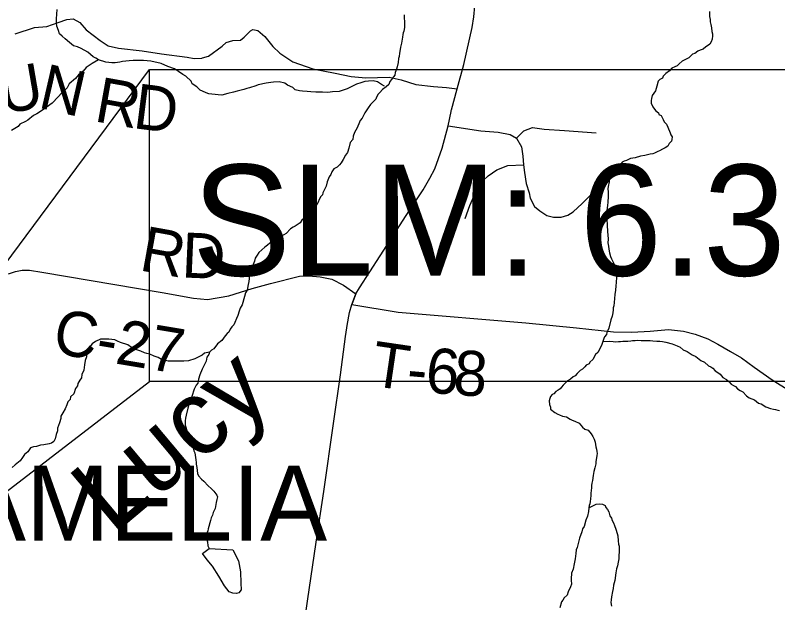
# Model space of a CAD drawing. Extents: x 0 to 39.3, y -3.9 to 22.
# Drawn here: x 5.137 to 6.099, y 18.467 to 19.208 of the extents above; entities that cross this region are included whole.
import ezdxf

# ---------------------------------------------------------------- set-up
doc = ezdxf.new("R2010")
doc.units = 0
for name, color, linetype in [('GM_X_Corporation_Text', 7, 'Continuous'), ('GM_X_County_Road', 7, 'Continuous'), ('GM_X_County_Road_Text', 7, 'Continuous'), ('GM_X_Minor_Lake', 7, 'Continuous'), ('GM_X_Minor_River', 7, 'Continuous'), ('GM_X_Minor_River_Text', 7, 'Continuous'), ('GM_X_State_Route', 7, 'Continuous'), ('GM_X_Township_Road', 7, 'Continuous'), ('GM_X_Township_Road_Text', 7, 'Continuous'), ('SH_Text', 7, 'Continuous')]:
    doc.layers.add(name, color=color, linetype=linetype)

msp = doc.modelspace()

# ---------------------------------------------------------------- linework, layer by layer
at = {"layer": 'GM_X_County_Road'}
msp.add_line((5.56691, 18.85683), (5.56159, 18.84354), dxfattribs=at)
for points in [[(5.12824, 18.88192), (5.13704, 18.8851), (5.1458, 18.88677), (5.15489, 18.88653), (5.17036, 18.88423), (5.32226, 18.85848), (5.36186, 18.85135), (5.3797, 18.84956), (5.4064, 18.85412), (5.43606, 18.86347), (5.45889, 18.86989), (5.49574, 18.87911), (5.50749, 18.87956), (5.52185, 18.87805), (5.5363, 18.87524), (5.55128, 18.86775), (5.56691, 18.85683)], [(5.56159, 18.84354), (5.62006, 18.83388), (5.78139, 18.82038), (5.84509, 18.81404), (5.8917, 18.80892), (5.91489, 18.80843), (5.93834, 18.80985), (5.96146, 18.81204), (5.9802, 18.80954), (5.99488, 18.8061), (6.01112, 18.79985), (6.02361, 18.7933), (6.03954, 18.78393), (6.0536, 18.77612), (6.06953, 18.76425), (6.09202, 18.74832), (6.11453, 18.73458)]]:
    msp.add_lwpolyline(points, dxfattribs=at)
at = {"layer": 'GM_X_Minor_Lake'}
msp.add_line((5.37322, 18.52915), (5.38151, 18.53579), dxfattribs=at)
msp.add_lwpolyline([(5.38151, 18.53579), (5.4117, 18.5338), (5.41869, 18.52), (5.42112, 18.50627), (5.42163, 18.49182), (5.42187, 18.48345), (5.41915, 18.47969), (5.41609, 18.47899), (5.41153, 18.47907), (5.407, 18.48105), (5.40104, 18.48837), (5.39365, 18.50066), (5.38588, 18.51334), (5.37918, 18.52144), (5.37322, 18.52915)], dxfattribs=at)
at = {"layer": 'GM_X_Minor_River'}
for points in [[(5.60269, 19.11877), (5.5993, 19.12073), (5.59404, 19.12425), (5.58874, 19.12548), (5.58265, 19.12521), (5.57808, 19.12453), (5.57311, 19.1231), (5.56776, 19.12129), (5.56086, 19.11799), (5.55587, 19.11541), (5.54556, 19.11217), (5.53718, 19.11156), (5.53147, 19.1109), (5.52463, 19.11102), (5.51627, 19.11116), (5.50981, 19.11166), (5.50526, 19.11212), (5.49956, 19.1126), (5.49577, 19.11305), (5.49009, 19.11429), (5.48709, 19.117), (5.48068, 19.12016), (5.4773, 19.1225), (5.4701, 19.12415), (5.46288, 19.12389), (5.45945, 19.12357), (5.45335, 19.12254), (5.44343, 19.12043), (5.44037, 19.11935), (5.43234, 19.11683), (5.42928, 19.11574), (5.42546, 19.11467), (5.41706, 19.11253), (5.41248, 19.11109), (5.40523, 19.10932), (5.39759, 19.10755), (5.39303, 19.10763), (5.38127, 19.10898), (5.37787, 19.11018), (5.37334, 19.11254), (5.37032, 19.11373), (5.36621, 19.11799), (5.36019, 19.12152), (5.35873, 19.12497), (5.35199, 19.13117), (5.34823, 19.13352), (5.34297, 19.13742), (5.33808, 19.14054), (5.32939, 19.14374), (5.32108, 19.14731), (5.30783, 19.1502), (5.29872, 19.15112), (5.2915, 19.15125), (5.28579, 19.15097), (5.28046, 19.15068), (5.27246, 19.14968), (5.26903, 19.14898), (5.26294, 19.14833), (5.25875, 19.14803), (5.25116, 19.14892), (5.24209, 19.15212), (5.2387, 19.15408), (5.23531, 19.15566), (5.22856, 19.16149), (5.22028, 19.1662), (5.21537, 19.16857), (5.21045, 19.16979), (5.2052, 19.17369), (5.19995, 19.17834), (5.19621, 19.18183), (5.19283, 19.18456), (5.19139, 19.18915), (5.1892, 19.19451), (5.18889, 19.1987), (5.18897, 19.20364), (5.18993, 19.21541)], [(5.62778, 19.20884), (5.62772, 19.20542), (5.628, 19.19933), (5.62831, 19.19514), (5.62827, 19.19286), (5.62743, 19.18831), (5.62663, 19.18604)], [(6.01296, 19.2131), (6.01323, 19.20663), (6.01393, 19.20281), (6.01388, 19.19977), (6.01458, 19.19633), (6.01565, 19.19213), (6.01595, 19.18756), (6.01667, 19.18489), (6.01701, 19.18222), (6.01655, 19.17804)], [(5.62663, 19.18604), (5.62622, 19.18377), (5.6254, 19.18036), (5.62452, 19.17315), (5.62329, 19.16785), (5.62286, 19.16482), (5.62202, 19.16026), (5.62157, 19.15609), (5.62076, 19.15344), (5.6203, 19.1485), (5.61907, 19.1432), (5.61788, 19.14018), (5.61629, 19.13603), (5.61585, 19.13261), (5.61429, 19.13036), (5.61158, 19.12736), (5.60963, 19.12473), (5.60843, 19.12095), (5.60496, 19.11797), (5.60034, 19.11463), (5.59686, 19.11089), (5.59492, 19.10864), (5.59295, 19.10487), (5.59177, 19.10223), (5.58829, 19.09849), (5.58519, 19.0955), (5.58208, 19.09137), (5.57817, 19.08497), (5.57464, 19.07819), (5.57231, 19.07557), (5.57151, 19.0733), (5.56835, 19.06613), (5.56522, 19.06048), (5.56323, 19.05557), (5.56278, 19.0514), (5.55968, 19.04765), (5.55804, 19.04045), (5.55605, 19.03516), (5.55371, 19.03178), (5.55057, 19.02613), (5.54822, 19.02199), (5.5459, 19.01936), (5.54319, 19.01675), (5.53897, 19.01454), (5.53663, 19.01078), (5.53505, 19.00739), (5.5331, 19.00438), (5.53071, 18.99795), (5.5291, 18.99266), (5.52673, 18.98775), (5.52516, 18.98436), (5.52473, 18.9817), (5.52241, 18.97946), (5.52084, 18.97645), (5.51886, 18.97154), (5.5173, 18.96928), (5.51422, 18.96706), (5.51228, 18.96443), (5.50992, 18.95991), (5.50797, 18.95728), (5.5045, 18.9543), (5.50142, 18.95207), (5.49872, 18.94983), (5.49639, 18.94645), (5.49408, 18.94459), (5.49024, 18.94237), (5.48755, 18.9409), (5.48447, 18.93867), (5.47867, 18.93307), (5.47598, 18.93122), (5.47254, 18.92975), (5.47023, 18.92827), (5.46676, 18.92529), (5.46214, 18.92195), (5.45832, 18.92088), (5.45523, 18.91827), (5.45177, 18.91567), (5.44791, 18.91231), (5.44443, 18.90895), (5.44209, 18.90557), (5.43975, 18.90181), (5.43893, 18.89802), (5.43616, 18.8916), (5.43417, 18.88631), (5.43254, 18.88025), (5.43165, 18.87228), (5.43083, 18.8685), (5.42956, 18.86129), (5.42761, 18.8579), (5.42601, 18.85337), (5.42317, 18.84276), (5.42082, 18.83862), (5.41961, 18.83484), (5.418, 18.82954), (5.41604, 18.82578), (5.41406, 18.82086), (5.41287, 18.81784), (5.41016, 18.81523), (5.40821, 18.81222), (5.40662, 18.80844), (5.40432, 18.80696)], [(6.01655, 19.17804), (6.01498, 19.17465), (6.01341, 19.17164), (6.01071, 19.16978), (6.00841, 19.1683), (6.00494, 19.16532), (6.00112, 19.16425), (5.99843, 19.16277), (5.99458, 19.1598), (5.99152, 19.15909), (5.98689, 19.15461), (5.97845, 19.15019), (5.97459, 19.14684), (5.97227, 19.14422), (5.96921, 19.14313), (5.96537, 19.14129), (5.96266, 19.13792), (5.95804, 19.13458), (5.95456, 19.13122), (5.95376, 19.12895), (5.95031, 19.12711), (5.94837, 19.12486), (5.94637, 19.11881), (5.94474, 19.11275), (5.94085, 19.10711), (5.93964, 19.10333), (5.93922, 19.10068), (5.93954, 19.09725), (5.94136, 19.09265), (5.94509, 19.08803), (5.94846, 19.0853), (5.94919, 19.08301), (5.95183, 19.08182), (5.95441, 19.07683), (5.95587, 19.07376), (5.95886, 19.07067), (5.96033, 19.06722), (5.96324, 19.05994), (5.96434, 19.05726), (5.96582, 19.05495), (5.96538, 19.05154), (5.96497, 19.04926), (5.96225, 19.04627), (5.9603, 19.04326), (5.95722, 19.04103), (5.95377, 19.03919), (5.94993, 19.03698), (5.94764, 19.03626), (5.9438, 19.03404), (5.94151, 19.03332), (5.93808, 19.033), (5.93159, 19.03121), (5.92587, 19.03055), (5.91937, 19.02839), (5.91327, 19.02735), (5.90829, 19.02516), (5.90523, 19.02407), (5.90294, 19.02297), (5.9006, 19.01959), (5.89789, 19.01697), (5.89633, 19.01472), (5.89477, 19.01208), (5.89246, 19.01022), (5.88976, 19.00799), (5.88857, 19.00497), (5.88662, 19.00196), (5.88655, 18.99816), (5.88531, 18.99209), (5.88488, 18.98906), (5.8852, 18.98563), (5.8851, 18.97993), (5.88459, 18.97195), (5.88415, 18.96853), (5.88366, 18.96169), (5.88321, 18.95752), (5.88316, 18.95486), (5.88346, 18.95029), (5.88374, 18.9442), (5.88407, 18.94115), (5.88439, 18.93734), (5.88435, 18.93506), (5.88466, 18.93125), (5.88495, 18.92592), (5.88487, 18.92098), (5.88556, 18.91678), (5.88588, 18.91335), (5.88694, 18.90839), (5.88801, 18.90381), (5.88948, 18.90112), (5.89205, 18.89575), (5.89387, 18.89115), (5.89496, 18.88809), (5.89492, 18.88543), (5.89524, 18.882), (5.89555, 18.87781), (5.89544, 18.87097), (5.89498, 18.86679), (5.89451, 18.86148), (5.89366, 18.85579), (5.89273, 18.84591), (5.89228, 18.84174)], [(5.24209, 19.15212), (5.23403, 19.14732), (5.22633, 19.14213), (5.22246, 19.13764), (5.21668, 19.13317), (5.2128, 19.1283), (5.20508, 19.12159), (5.20234, 19.11669), (5.19538, 19.10997), (5.19112, 19.1051), (5.18338, 19.09725), (5.17145, 19.08833), (5.16415, 19.08389), (5.15993, 19.08168), (5.15299, 19.07572), (5.14992, 19.07426), (5.14264, 19.07096), (5.14069, 19.06795), (5.13224, 19.06278)], [(5.89228, 18.84174), (5.89148, 18.83909), (5.89144, 18.83681), (5.891, 18.83301), (5.89016, 18.82846), (5.88856, 18.82393), (5.8861, 18.81332), (5.88454, 18.81068), (5.88335, 18.80804), (5.88293, 18.80539), (5.8806, 18.80277), (5.8798, 18.8005), (5.87701, 18.79294), (5.87582, 18.78992), (5.8719, 18.78276), (5.86919, 18.78015), (5.86567, 18.77412), (5.86181, 18.77077), (5.86101, 18.7685), (5.85757, 18.76704), (5.85563, 18.76479), (5.85292, 18.7618), (5.84985, 18.75995), (5.84598, 18.75622), (5.84366, 18.75359), (5.84097, 18.75212), (5.8375, 18.74914), (5.83404, 18.74691), (5.83056, 18.74355), (5.82825, 18.74169), (5.8263, 18.73906), (5.82437, 18.73682), (5.82206, 18.73533), (5.81899, 18.73349), (5.81666, 18.73087), (5.81436, 18.72976), (5.81243, 18.72752), (5.81162, 18.72487), (5.81081, 18.72184), (5.81111, 18.71727), (5.81219, 18.71383), (5.81253, 18.71116), (5.81779, 18.70726), (5.82155, 18.70492), (5.82382, 18.70412), (5.82759, 18.70253), (5.83252, 18.70168), (5.83704, 18.69894), (5.83967, 18.69737), (5.84307, 18.69617), (5.84835, 18.69379), (5.85283, 18.68877), (5.85583, 18.68606), (5.85999, 18.68484), (5.86371, 18.68021), (5.86593, 18.67675), (5.8674, 18.67368), (5.86886, 18.66985), (5.86952, 18.66375), (5.87023, 18.6607), (5.87094, 18.65802), (5.87128, 18.65536), (5.87085, 18.6527), (5.87043, 18.65005), (5.86959, 18.6455), (5.86954, 18.64245), (5.86831, 18.63715), (5.86709, 18.63261), (5.86625, 18.62768), (5.86538, 18.62123), (5.86457, 18.6182), (5.86414, 18.61516), (5.86409, 18.6125), (5.86364, 18.60833), (5.86322, 18.60567), (5.86316, 18.60225), (5.86272, 18.59845), (5.86228, 18.59504), (5.86185, 18.592), (5.86105, 18.58973), (5.86062, 18.5867), (5.86016, 18.58214), (5.85892, 18.57646), (5.85694, 18.57155), (5.8549, 18.56322), (5.85295, 18.56021), (5.85174, 18.55643), (5.84895, 18.54849), (5.84609, 18.53675), (5.8449, 18.53372), (5.84444, 18.52917), (5.84357, 18.52272), (5.84232, 18.51627), (5.84107, 18.50945), (5.83908, 18.50454), (5.83905, 18.50226), (5.83862, 18.4996), (5.83856, 18.4958), (5.83885, 18.49047), (5.83765, 18.48707), (5.83451, 18.48104)], [(5.40432, 18.80696), (5.40199, 18.80396), (5.3977, 18.79795), (5.39231, 18.79386), (5.38764, 18.78748), (5.38457, 18.78563), (5.38187, 18.7834), (5.38106, 18.78037), (5.37872, 18.77699), (5.37787, 18.77168), (5.37276, 18.76188), (5.36998, 18.7547), (5.36799, 18.74903), (5.36715, 18.7441), (5.3652, 18.74147), (5.36284, 18.73657), (5.35964, 18.7275), (5.35883, 18.72447), (5.35762, 18.72031), (5.35605, 18.71729), (5.35483, 18.71275), (5.35278, 18.70365), (5.35157, 18.69987), (5.35114, 18.69684), (5.35143, 18.69113), (5.3525, 18.6873), (5.35393, 18.68195), (5.35571, 18.67432), (5.35756, 18.67162), (5.35866, 18.66932), (5.35937, 18.66626), (5.36159, 18.66242), (5.36228, 18.6586), (5.36338, 18.6563), (5.36409, 18.65325), (5.36442, 18.6502), (5.36476, 18.64753), (5.36508, 18.6441), (5.36542, 18.64181), (5.36611, 18.63762), (5.36674, 18.63), (5.36822, 18.62731), (5.37195, 18.62306), (5.37494, 18.62035), (5.38017, 18.61455), (5.3843, 18.61143), (5.38766, 18.60795), (5.39138, 18.60294), (5.3921, 18.60065), (5.39128, 18.59724), (5.39046, 18.59345), (5.3892, 18.58624), (5.38683, 18.58096), (5.38601, 18.57755), (5.38405, 18.57416), (5.38323, 18.57075), (5.3804, 18.56053), (5.37998, 18.55788), (5.37918, 18.55561), (5.37912, 18.55219), (5.37832, 18.54954), (5.37865, 18.54687), (5.37937, 18.5442), (5.38004, 18.53886), (5.38151, 18.53579)], [(5.38184, 18.78327), (5.37576, 18.78198), (5.37268, 18.77938), (5.36348, 18.77497), (5.35546, 18.77245), (5.34974, 18.77179), (5.34328, 18.7719), (5.33377, 18.77169), (5.32997, 18.77176), (5.32467, 18.77299), (5.32127, 18.77419), (5.31713, 18.77655), (5.31221, 18.77816), (5.30693, 18.78053), (5.30315, 18.78174), (5.30012, 18.78255), (5.29521, 18.78454), (5.2903, 18.78615), (5.28351, 18.78931), (5.279, 18.79243), (5.26955, 18.79564), (5.26577, 18.79723), (5.26238, 18.79881), (5.25517, 18.7997), (5.25175, 18.79976), (5.24794, 18.79945), (5.24452, 18.79951), (5.23839, 18.79657), (5.23378, 18.79361), (5.22989, 18.78835), (5.22672, 18.7808), (5.22666, 18.77738), (5.22506, 18.77284), (5.22421, 18.76715), (5.22377, 18.76374), (5.22334, 18.7607), (5.22096, 18.75504), (5.22051, 18.75086), (5.21856, 18.74786), (5.21583, 18.74372), (5.2154, 18.74068), (5.21306, 18.7373), (5.21067, 18.73088), (5.2068, 18.72676), (5.20637, 18.72373), (5.20328, 18.72074), (5.20207, 18.71696), (5.20008, 18.71166), (5.19696, 18.70678), (5.19461, 18.70263), (5.19456, 18.69959), (5.19256, 18.69392), (5.19017, 18.6875), (5.19011, 18.68407), (5.18852, 18.67954), (5.18728, 18.67385), (5.1857, 18.67046), (5.18263, 18.66861), (5.17957, 18.66752), (5.17309, 18.6665), (5.1689, 18.66581), (5.16355, 18.66438), (5.15974, 18.66369), (5.1563, 18.66261), (5.15279, 18.65734), (5.14855, 18.654), (5.1462, 18.65023), (5.14309, 18.6461), (5.13693, 18.64127), (5.13307, 18.63791)], [(5.87837, 18.79662), (5.88735, 18.79694), (5.89152, 18.79649), (5.89456, 18.79644), (5.89837, 18.79675), (5.90065, 18.79671), (5.90369, 18.79704), (5.90712, 18.79698), (5.91016, 18.7973), (5.91359, 18.79762), (5.91588, 18.79796), (5.9193, 18.7979), (5.92196, 18.79824), (5.92691, 18.79815), (5.93831, 18.79795), (5.94172, 18.79751), (5.94665, 18.79704), (5.95045, 18.79697), (5.95387, 18.79654), (5.95804, 18.7957), (5.96599, 18.79366), (5.97241, 18.79126), (5.97618, 18.78968), (5.97993, 18.78619), (5.98483, 18.7842), (5.99123, 18.7799), (5.99575, 18.77792), (6.00213, 18.77286), (6.00666, 18.7705), (6.0119, 18.76585), (6.01492, 18.76465), (6.01718, 18.76309), (6.02016, 18.75962), (6.02355, 18.75765), (6.02655, 18.7557), (6.0299, 18.75108), (6.03442, 18.74872), (6.03742, 18.74638), (6.04041, 18.7429), (6.04342, 18.74133), (6.04568, 18.73977), (6.04829, 18.73706), (6.05168, 18.7351), (6.05507, 18.73314), (6.05992, 18.72811), (6.06293, 18.72577), (6.06633, 18.72457), (6.06972, 18.72299), (6.07498, 18.7191), (6.07838, 18.7179), (6.08402, 18.71437), (6.09007, 18.71236), (6.09386, 18.71116), (6.09613, 18.71074), (6.09916, 18.70992), (6.10143, 18.7095)], [(5.86062, 18.58669), (5.86982, 18.59148), (5.87401, 18.59179), (5.87819, 18.59172), (5.8812, 18.58976), (5.8823, 18.58746), (5.88415, 18.58476), (5.886, 18.58169), (5.88744, 18.57672), (5.8893, 18.57402), (5.89, 18.57097), (5.89185, 18.56789), (5.89332, 18.56482), (5.89476, 18.55985), (5.89657, 18.5545), (5.89728, 18.55144), (5.89794, 18.54534), (5.89825, 18.54115), (5.89896, 18.53848), (5.89891, 18.53506), (5.89921, 18.53049), (5.89878, 18.52745), (5.89869, 18.52251), (5.89786, 18.51834), (5.89703, 18.51379), (5.89582, 18.51001), (5.89498, 18.50508), (5.89367, 18.49521), (5.89205, 18.48953), (5.89161, 18.48536), (5.89078, 18.48157), (5.88915, 18.47475), (5.88908, 18.47095), (5.88864, 18.46753), (5.88933, 18.46296)], [(5.83451, 18.48104), (5.8333, 18.47687), (5.82982, 18.47351), (5.82787, 18.4705), (5.82631, 18.46825), (5.82428, 18.46068)]]:
    msp.add_lwpolyline(points, dxfattribs=at)
at = {"layer": 'GM_X_State_Route'}
msp.add_line((5.56159, 18.84354), (5.56691, 18.85683), dxfattribs=at)
for points in [[(5.68714, 19.08789), (5.6874, 19.08886), (5.69468, 19.11543), (5.70308, 19.14607), (5.71363, 19.19295), (5.71549, 19.2064), (5.71709, 19.21966)], [(5.56691, 18.85683), (5.57155, 18.86424), (5.59762, 18.90493), (5.63029, 18.95541), (5.65188, 18.98802), (5.66007, 19.00284), (5.66653, 19.0146), (5.67582, 19.04065), (5.68308, 19.06869), (5.68688, 19.08691), (5.68714, 19.08789)], [(5.55541, 18.8138), (5.55585, 18.81676), (5.55891, 18.83307), (5.56159, 18.84354)], [(5.39661, 17.70778), (5.40454, 17.74242), (5.41021, 17.78467), (5.41899, 17.85362), (5.42754, 17.92239), (5.43621, 17.99379), (5.445, 18.05325), (5.44884, 18.08292), (5.45585, 18.13046), (5.45728, 18.14137), (5.4643, 18.19014), (5.47518, 18.26261), (5.48537, 18.33475), (5.4953, 18.39669), (5.50563, 18.46932), (5.5167, 18.54341), (5.52615, 18.6076), (5.53853, 18.69319), (5.54726, 18.75446), (5.55381, 18.80293), (5.55541, 18.8138)]]:
    msp.add_lwpolyline(points, dxfattribs=at)
at = {"layer": 'GM_X_Township_Road'}
for points in [[(5.1366, 19.18461), (5.16121, 19.19258), (5.17685, 19.19389), (5.19102, 19.19909), (5.20202, 19.203), (5.21013, 19.20372), (5.21824, 19.19909), (5.2262, 19.18982), (5.24407, 19.17637), (5.25428, 19.1696), (5.2672, 19.16677), (5.29688, 19.16341), (5.32142, 19.15948), (5.35381, 19.15536), (5.36259, 19.15367), (5.37238, 19.15402), (5.37324, 19.15428)], [(5.37324, 19.15428), (5.38093, 19.15661), (5.39792, 19.16933), (5.40327, 19.17396), (5.41145, 19.17619), (5.42107, 19.17684), (5.42596, 19.18055), (5.43032, 19.18517), (5.43361, 19.18873), (5.43684, 19.1903), (5.44303, 19.18876), (5.45194, 19.18144), (5.46218, 19.16871), (5.4709, 19.16043), (5.48733, 19.14931), (5.51265, 19.14048), (5.5408, 19.13498), (5.56096, 19.13099), (5.57931, 19.12909), (5.60888, 19.13022), (5.624, 19.12667), (5.64234, 19.12094), (5.66475, 19.11835), (5.68095, 19.11688), (5.69468, 19.11543)], [(5.68308, 19.06869), (5.72436, 19.06254), (5.7462, 19.06055), (5.76154, 19.05784)], [(5.76948, 19.05333), (5.77869, 19.06236), (5.7897, 19.06651), (5.80432, 19.06434), (5.82995, 19.0629), (5.87008, 19.05985)], [(5.76154, 19.05784), (5.76948, 19.05333), (5.7758, 19.04214), (5.7776, 19.03041), (5.77833, 19.01958), (5.77959, 19.01001), (5.78157, 18.99593), (5.78537, 18.9842), (5.78684, 18.97752), (5.79234, 18.96718), (5.79905, 18.96137), (5.80767, 18.95553), (5.81634, 18.95349), (5.82581, 18.9537), (5.83419, 18.95584), (5.84108, 18.96027), (5.85226, 18.97071), (5.87386, 18.99273), (5.88388, 19.0028), (5.89155, 19.00761), (5.90147, 19.01199), (5.91332, 19.01309), (5.92381, 19.01085), (5.93359, 19.00658)], [(5.70486, 18.95171), (5.71064, 18.96831), (5.71569, 18.97968), (5.72111, 18.9916), (5.72742, 18.9999), (5.73356, 19.00586), (5.7448, 19.01339), (5.75847, 19.01849), (5.77833, 19.01958)]]:
    msp.add_lwpolyline(points, dxfattribs=at)
at = {"layer": 'SH_Text'}
for p, q in [((4.62313, 18.21994), (5.30617, 19.13968)), ((4.62349, 18.22042), (5.30617, 18.74639))]:
    msp.add_line(p, q, dxfattribs=at)
msp.add_lwpolyline([(5.30617, 19.13968), (6.76414, 19.13968), (6.76414, 18.74639), (5.30617, 18.74639)], close=True, dxfattribs=at)

# ---------------------------------------------------------------- texts
at = {"layer": 'GM_X_Corporation_Text'}
msp.add_text('AMELIA', height=0.094697, rotation=0.00001, dxfattribs=at).set_placement((5.06604, 18.54546))
at = {"layer": 'GM_X_County_Road_Text'}
for s, height, rotation, p in [('R', 0.05682, 349.83444, (5.29203, 18.88671)), ('D', 0.05682, 357.57297, (5.34614, 18.87757)), ('C-27', 0.056818, 350.54206, (5.18249, 18.78238))]:
    msp.add_text(s, height=height, rotation=rotation, dxfattribs=at).set_placement(p)
at = {"layer": 'GM_X_Minor_River_Text'}
msp.add_text('Lucy', height=0.094698, rotation=40.00345, dxfattribs=at).set_placement((5.25975, 18.55167))
at = {"layer": 'GM_X_Township_Road_Text'}
for s, rotation, p in [('U', 9.76437, (5.12092, 19.08342)), ('N', 347.06027, (5.16429, 19.09206)), ('R', 349.80447, (5.23519, 19.07476)), ('D', 352.77227, (5.28424, 19.06602)), ('T', 351.61715, (5.58394, 18.74126)), ('6', 355.49767, (5.6534, 18.73258)), ('8', 355.67377, (5.68848, 18.72982)), ('-', 355.05487, (5.62968, 18.73463))]:
    msp.add_text(s, height=0.05682, rotation=rotation, dxfattribs=at).set_placement(p)
at = {"layer": 'SH_Text'}
msp.add_text('SLM: 6.35-6.37', height=0.14, dxfattribs=at).set_placement((5.35997, 18.87976))

doc.saveas('drawing.dxf')
